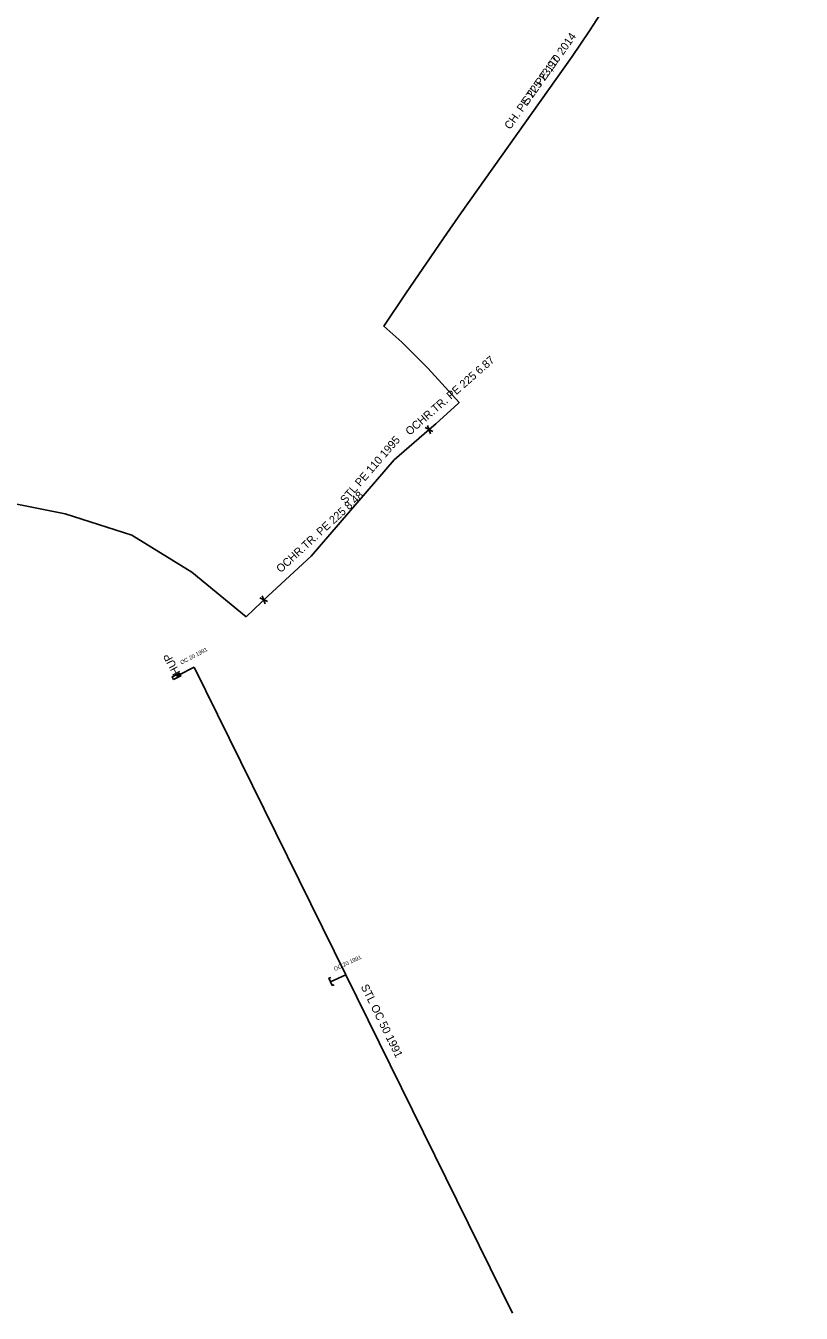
# Model space of a CAD drawing. Extents: x -734239 to -733693, y -1053757 to -1053379.
# Drawn here: x -733929.8 to -733832.9, y -1053683.4 to -1053522.5 of the extents above; entities that cross this region are included whole.
import ezdxf

# ---------------------------------------------------------------- set-up
doc = ezdxf.new("R2010")
doc.units = 0
for name, color, linetype in [('ST OP Chráni_ka - provoz', 7, 'Continuous'), ('ST Úsek p_ípojky - provoz', 7, 'Continuous'), ('ST Úsek plynovodu - provoz', 7, 'Continuous'), ('ST_HUP_22_23_popis', 7, 'Continuous'), ('Vrstva 1', 7, 'Continuous')]:
    doc.layers.add(name, color=color, linetype=linetype)

msp = doc.modelspace()

# ---------------------------------------------------------------- linework, layer by layer
at = {"layer": 'ST OP Chráni_ka - provoz'}
for points in [[(-733875.36, -1053545.88), (-733861.49, -1053526.33)], [(-733879.38, -1053572.97), (-733878.55, -1053572.24)], [(-733883.73, -1053576.76), (-733879.38, -1053572.97)], [(-733894.12, -1053588.78), (-733883.73, -1053576.76)], [(-733900.05, -1053594.24), (-733894.12, -1053588.78)], [(-733900.33, -1053594.55), (-733900.05, -1053594.24)]]:
    msp.add_lwpolyline(points, dxfattribs=at)
at = {"layer": 'ST Úsek p_ípojky - provoz'}
for points in [[(-733908.75, -1053602.65), (-733910.7, -1053603.67), (-733910.96, -1053603.81)], [(-733889.78, -1053641.1), (-733891.69, -1053641.99)]]:
    msp.add_lwpolyline(points, dxfattribs=at)
at = {"layer": 'ST Úsek plynovodu - provoz'}
for points in [[(-733875.74, -1053569.69), (-733875.63, -1053569.59), (-733879.51, -1053565.3), (-733882.77, -1053562.02), (-733885.03, -1053560.05), (-733882.33, -1053555.99), (-733877.55, -1053548.98), (-733875.36, -1053545.88), (-733861.49, -1053526.33), (-733859.34, -1053523.11), (-733856.03, -1053517.99), (-733852.8, -1053513.59), (-733844.53, -1053512.72), (-733838.84, -1053517.05), (-733833.42, -1053520.89), (-733832.99, -1053521.28), (-733832.95, -1053521.31), (-733832.85, -1053521.2)], [(-733875.74, -1053569.69), (-733878.55, -1053572.24), (-733879.38, -1053572.97), (-733883.73, -1053576.76), (-733894.12, -1053588.78), (-733900.05, -1053594.24), (-733900.33, -1053594.55), (-733902.26, -1053596.38)], [(-733902.26, -1053596.38), (-733909.04, -1053590.79), (-733916.55, -1053586.18), (-733924.88, -1053583.48), (-733950.53, -1053578.36), (-733958.24, -1053577.23), (-733977.56, -1053577.32), (-733989.55, -1053577.74), (-733990.87, -1053578.54), (-733991.41, -1053578.81), (-733992.01, -1053579.18), (-733992.91, -1053579.78)], [(-733868.93, -1053683.41), (-733889.78, -1053641.1), (-733908.75, -1053602.65)]]:
    msp.add_lwpolyline(points, dxfattribs=at)
at = {"layer": 'Vrstva 1'}
for p, q in [((-733879.86, -1053572.72), (-733878.9, -1053573.22)), ((-733879.56, -1053572.46), (-733879.2, -1053573.48)), ((-733900.24, -1053593.74), (-733899.86, -1053594.74)), ((-733900.54, -1053594.01), (-733899.56, -1053594.47))]:
    msp.add_line(p, q, dxfattribs=at)
msp.add_lwpolyline([(-733911.31, -1053604.22), (-733911.49, -1053603.87), (-733910.61, -1053603.4), (-733910.42, -1053603.75)], close=True, dxfattribs=at)
msp.add_lwpolyline([(-733891.25, -1053642.34), (-733891.48, -1053642.44), (-733891.9, -1053641.53), (-733891.67, -1053641.43)], dxfattribs=at)

# ---------------------------------------------------------------- texts
at = {"layer": 'ST OP Chráni_ka - provoz'}
for s, rotation, p in [('CH. PE 225 23,97', 54.6457, (-733869.24, -1053535.53)), ('OCHR.TR. PE 225 6.87', 41.0645, (-733881.8, -1053573.75)), ('OCHR.TR. PE 225 8.48', 42.6371, (-733897.92, -1053590.92))]:
    msp.add_text(s, height=1, rotation=rotation, dxfattribs=at).set_placement(p)
at = {"layer": 'ST Úsek p_ípojky - provoz'}
for rotation, p in [(27.7283, (-733910.32, -1053602.34)), (24.88, (-733891.16, -1053640.64))]:
    msp.add_text('OC 20 1991', height=0.5, rotation=rotation, dxfattribs=at).set_placement(p)
at = {"layer": 'ST Úsek plynovodu - provoz'}
for s, rotation, p in [('STL PE 110 2014', 54.6457, (-733867.04, -1053532.43)), ('STL PE 110 1995', 49.1601, (-733889.83, -1053582.29)), ('STL OC 50 1991', 296.2396, (-733887.94, -1053642.58))]:
    msp.add_text(s, height=1, rotation=rotation, dxfattribs=at).set_placement(p)
at = {"layer": 'ST_HUP_22_23_popis'}
msp.add_text('HUP', height=1, rotation=118, dxfattribs=at).set_placement((-733910.46, -1053603.31))

doc.saveas('drawing.dxf')
